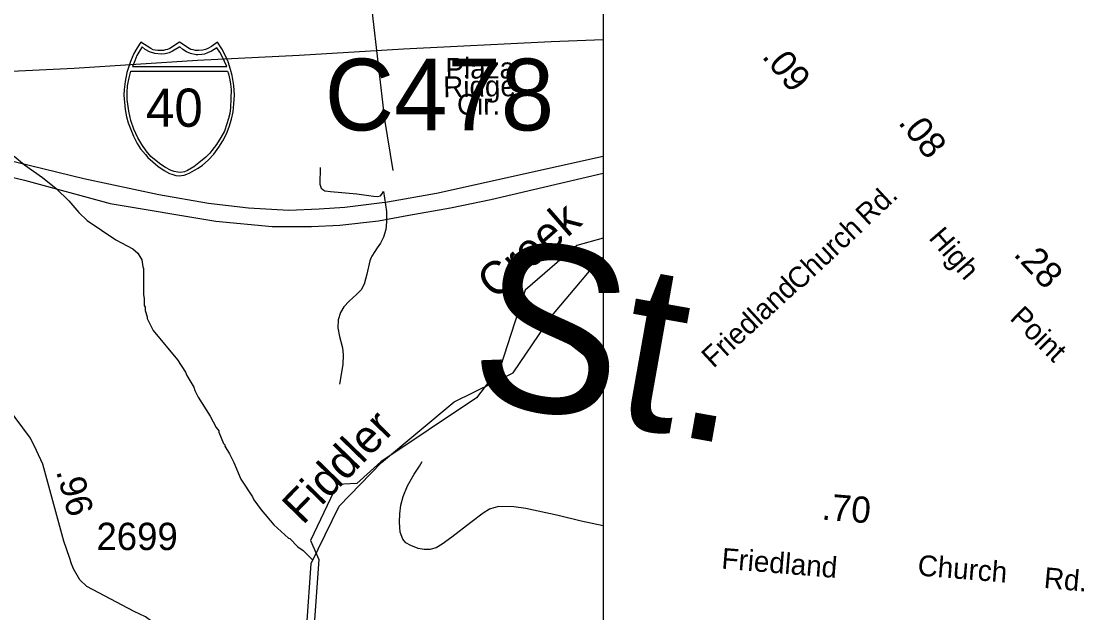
# Model space of a CAD drawing. Extents: x 1553981 to 1780076, y 812965 to 996873.
# Drawn here: x 1636043 to 1636650, y 846563 to 846901 of the extents above; entities that cross this region are included whole.
import ezdxf

# ---------------------------------------------------------------- set-up
doc = ezdxf.new("R2010")
doc.units = 0
for name, color, linetype in [('Default', 7, 'Continuous'), ('Exist Geographical Mountain Summit Label', 7, 'Continuous'), ('Exist Hydrographic Creek Single Shore', 7, 'Continuous'), ('Exist Hydrographic Creek Single Shore Label', 7, 'Continuous'), ('Exist Hydrographic Misc Water Feature', 7, 'Continuous'), ('Exist Road Non-System Type 51 Label', 7, 'Continuous'), ('Exist Road Primary Interstate Divided Center Attributed', 7, 'Continuous'), ('Exist Road Primary Interstate Shield CELL', 7, 'Continuous'), ('Exist Road Secondary Mileage Hundredths English Label', 7, 'Continuous'), ('Exist Road Secondary Structure Culvert Number Label', 7, 'Continuous'), ('Exist Road Secondary Type 51 Attributed', 7, 'Continuous'), ('Exist Road Secondary Type 51 Number Label', 7, 'Continuous'), ('Exist Utilities Electrical Transmission Line', 7, 'Continuous'), ('Map Preparation Border Antique Large Shape', 7, 'Continuous'), ('Map Preparation Border County Name Lower Right Label', 7, 'Continuous'), ('Map Preparation Border FIPS Code Label', 7, 'Continuous'), ('Map Preparation Border Revised Sign Off', 7, 'Continuous')]:
    doc.layers.add(name, color=color, linetype=linetype)

msp = doc.modelspace()

# ---------------------------------------------------------------- linework, layer by layer
at = {"layer": 'Default'}
msp.add_lwpolyline([(1632323.05, 848155.4), (1636375.85, 848155.4), (1636375.85, 845052.3), (1632323.05, 845052.3)], close=True, dxfattribs=at)
at = {"layer": 'Exist Hydrographic Creek Single Shore'}
msp.add_lwpolyline([(1636029.59, 846201.56), (1636078.51, 846261.77), (1636143.03, 846320.63), (1636154.6, 846354.87), (1636172.74, 846405.26), (1636203.88, 846520.44), (1636208.88, 846591.32), (1636224.87, 846624.22), (1636249.13, 846649.17), (1636290.69, 846683.7), (1636324.36, 846700.36), (1636346.42, 846732.9), (1636373.1, 846764.51), (1636375.85, 846766.54)], dxfattribs=at)
at = {"layer": 'Exist Hydrographic Misc Water Feature'}
msp.add_lwpolyline([(1636039.06, 846824.23), (1636045.02, 846819.18), (1636055.21, 846812.11), (1636063.15, 846805.8), (1636070.34, 846798.74), (1636076.04, 846791.95), (1636080.76, 846787.42), (1636097.16, 846776.3), (1636106.87, 846771.22), (1636109.84, 846768.7), (1636112.07, 846764.93), (1636112.54, 846760.93), (1636113.03, 846759.93), (1636112.93, 846744.94), (1636113.41, 846742.94), (1636113.38, 846738.94), (1636113.88, 846737.94), (1636113.86, 846735.94), (1636115.08, 846732.43), (1636115.08, 846731.43), (1636118.53, 846724.66), (1636132.39, 846707.81), (1636137.09, 846700.78), (1636137.83, 846698.77), (1636141.78, 846692.25), (1636142.26, 846690.24), (1636144.24, 846686.48), (1636151.14, 846675.69), (1636154.6, 846669.16), (1636156.08, 846667.15), (1636156.08, 846666.4), (1636158.78, 846659.88), (1636159.53, 846659.13), (1636159.51, 846658.38), (1636162.23, 846654.11), (1636164.7, 846649.09), (1636168.62, 846639.57), (1636175.3, 846629.52), (1636176.03, 846627.77), (1636180.24, 846621.99), (1636187.43, 846613.44), (1636195.86, 846605.87), (1636196.61, 846605.62), (1636201.32, 846600.83), (1636204.3, 846598.81), (1636209.35, 846593.69)], dxfattribs=at)
at = {"layer": 'Exist Road Primary Interstate Divided Center Attributed'}
for points in [[(1636375.85, 846824.07), (1636280.45, 846802.79), (1636252.47, 846798), (1636228.16, 846794.86), (1636213.35, 846793.96), (1636196, 846793.21), (1636173.1, 846794.41), (1636150.19, 846797.22), (1636121.8, 846802.2), (1636078.89, 846811.33), (1635970.16, 846837.8), (1635944.57, 846843.33), (1635918.77, 846847.37), (1635895.43, 846849.32), (1635871.9, 846850.24), (1635849.3, 846848.57), (1635828.29, 846845.97), (1635812.46, 846843.48)], [(1635819.59, 846832.32), (1635829.38, 846834.1), (1635855.63, 846836.6), (1635877.77, 846837.95), (1635891.84, 846838.7), (1635911.14, 846837.05), (1635923.18, 846835.85), (1635945.92, 846832.86), (1635968.81, 846828.52), (1636045.04, 846810.42), (1636093.96, 846797.08), (1636154.34, 846787.05), (1636186.57, 846784.09), (1636209.09, 846783.94), (1636225.24, 846784.84), (1636247.39, 846787.23), (1636264.74, 846790.52), (1636288.53, 846794.71), (1636311.57, 846799.5), (1636375.85, 846814.44)]]:
    msp.add_lwpolyline(points, dxfattribs=at)
at = {"layer": 'Exist Road Primary Interstate Shield CELL'}
for points in [[(1636133.49, 846813.02), (1636134.67, 846813.14), (1636136.27, 846813.45), (1636137.82, 846813.96), (1636139.58, 846814.74), (1636142.18, 846816.18), (1636144.28, 846817.41), (1636146.7, 846819.03), (1636149.96, 846821.99), (1636153.22, 846825.42), (1636156.09, 846829.3), (1636158.37, 846832.93), (1636160.38, 846837.07), (1636162.06, 846840.94), (1636163.39, 846845.35), (1636164.28, 846849.63), (1636164.72, 846854.09), (1636165.02, 846859.04), (1636164.68, 846864.61), (1636163.72, 846870.3), (1636162.81, 846873.85), (1636161.43, 846878.09), (1636160.3, 846880.8), (1636157.7, 846885.6), (1636155.36, 846889.3), (1636151.95, 846886.91), (1636149.73, 846885.73), (1636148.38, 846885.12), (1636146.98, 846884.85), (1636144.42, 846884.54), (1636142.81, 846884.61), (1636141.32, 846884.95), (1636140.05, 846885.22), (1636139.02, 846885.73), (1636133.49, 846889.3), (1636127.96, 846885.73), (1636126.8, 846885.19), (1636125.61, 846884.95), (1636124.46, 846884.63), (1636122.57, 846884.54), (1636121.13, 846884.58), (1636119.64, 846884.85), (1636118.47, 846885.09), (1636117.16, 846885.73), (1636111.52, 846889.3), (1636109.3, 846886.09), (1636107.49, 846882.91), (1636105.57, 846878.42), (1636104.38, 846874.94), (1636103.53, 846872.08), (1636102.48, 846866.84), (1636101.95, 846862.27), (1636101.85, 846859.04), (1636102.44, 846850.98), (1636103.32, 846846.68), (1636104.23, 846843.21), (1636107.21, 846835.7), (1636109.45, 846831.5), (1636111.38, 846828.48), (1636114.08, 846825.09), (1636115.54, 846823.46), (1636121.14, 846818.57), (1636124.88, 846816.01), (1636127.87, 846814.4), (1636129.27, 846813.87), (1636131.47, 846813.25)], [(1636112.19, 846886.71), (1636110.81, 846884.6), (1636109.23, 846881.74), (1636107.96, 846878.78), (1636106.67, 846875.51), (1636160.61, 846875.49), (1636159.36, 846878.29), (1636158.01, 846881.11), (1636156.6, 846883.68), (1636154.89, 846886.17), (1636151.86, 846884.26), (1636149.66, 846883.22), (1636147.89, 846882.61), (1636146.39, 846882.27), (1636144.07, 846882.09), (1636143.03, 846882.15), (1636139.78, 846882.88), (1636137.59, 846883.78), (1636135.5, 846885.17), (1636133.81, 846886.77), (1636129.54, 846884.18), (1636127.64, 846883.34), (1636125.46, 846882.79), (1636123.08, 846882.49), (1636119.4, 846882.89), (1636116.51, 846883.88), (1636114.03, 846885.17)], [(1636160.93, 846872.83), (1636161.51, 846871.31), (1636162.3, 846867.92), (1636162.72, 846865.32), (1636163.15, 846862.32), (1636163, 846857.18), (1636162.75, 846851.86), (1636162.26, 846848.7), (1636161.61, 846845.84), (1636160.71, 846842.66), (1636159.27, 846838.43), (1636157.28, 846834.85), (1636154.8, 846830.87), (1636152.11, 846827.39), (1636150.95, 846825.94), (1636148.73, 846823.6), (1636144.71, 846820.37), (1636141.77, 846818.17), (1636138.24, 846816.09), (1636136.45, 846815.3), (1636134.37, 846814.86), (1636132.66, 846814.98), (1636130.58, 846815.53), (1636128.9, 846815.99), (1636125.22, 846817.98), (1636122.24, 846819.97), (1636117.27, 846824.05), (1636114.59, 846827.19), (1636112.08, 846830.86), (1636109.85, 846834.63), (1636107.46, 846839.59), (1636105.78, 846844.57), (1636104.56, 846849.96), (1636103.73, 846856.54), (1636103.64, 846860.55), (1636103.88, 846864.4), (1636104.25, 846866.42), (1636104.74, 846868.93), (1636105.72, 846872.8)]]:
    msp.add_lwpolyline(points, close=True, dxfattribs=at)
at = {"layer": 'Exist Road Secondary Type 51 Attributed'}
msp.add_lwpolyline([(1636189.85, 846353.59), (1636177.07, 846391.96), (1636172.68, 846404.92), (1636168.55, 846419.71), (1636158.56, 846448.82), (1636144.46, 846492.68), (1636127.42, 846543.3), (1636122.71, 846551.83), (1636118.36, 846557.06), (1636117.72, 846558.29), (1636114.19, 846560.94), (1636107.73, 846563.88), (1636080.7, 846578.28), (1636076.59, 846582.1), (1636073.06, 846588.28), (1636071.89, 846591.22), (1636070.71, 846594.75), (1636067.48, 846604.15), (1636055.44, 846648.25), (1636051.91, 846655.89), (1636048.38, 846662.95), (1636025.72, 846693.31)], dxfattribs=at)
at = {"layer": 'Exist Utilities Electrical Transmission Line'}
msp.add_lwpolyline([(1636375.85, 846890.8), (1636346.1, 846889.49), (1636261.6, 846885.32), (1636202.07, 846881.86), (1636143.83, 846878.86), (1636073.32, 846874.27), (1635989.55, 846870.34), (1635919.82, 846867.25), (1635837.31, 846863.83), (1635766.81, 846860.73), (1635738.73, 846851.35), (1635627.77, 846812.03), (1635508.32, 846769.31), (1635424.73, 846738.89), (1635323.32, 846702.95), (1635267.09, 846683.16), (1635250.28, 846696.63), (1635201.6, 846738.27), (1635122.5, 846804.31), (1635050.76, 846862.25), (1635014.93, 846892.22), (1635012.58, 846924.48)], dxfattribs=at)
at = {"layer": 'Map Preparation Border County Name Lower Right Label'}
for points in [[(1636255.73, 846816.12), (1636251, 846845.23), (1636243.79, 846907.75)], [(1636214.05, 846817.7), (1636213.76, 846808.2), (1636214.49, 846805.96), (1636215.47, 846805.19), (1636216.73, 846804.44), (1636219.97, 846803.93), (1636234.95, 846802.6), (1636244.43, 846801.28), (1636246.68, 846801.26), (1636248.44, 846801.5), (1636249.18, 846802.51), (1636250.19, 846803.99), (1636251.88, 846792.5), (1636251.99, 846786.74), (1636251.57, 846782.25), (1636250.29, 846778), (1636248.51, 846774.51), (1636246.62, 846771.78), (1636245.24, 846769.79), (1636243.49, 846767.05), (1636243.22, 846766.31), (1636242.48, 846764.3), (1636240.68, 846756.8), (1636239.13, 846751.08), (1636237.37, 846747.84), (1636234.86, 846745.09), (1636230.58, 846741.38), (1636227.59, 846738.14), (1636225.55, 846734.9), (1636224.29, 846730.67), (1636224.02, 846726.18), (1636224.97, 846721.15), (1636226.69, 846714.67), (1636227.16, 846710.65), (1636226.9, 846705.16), (1636225.07, 846693.91)], [(1636339.08, 846730.94), (1636367, 846708.85), (1636375.85, 846707.89)], [(1636375.85, 846612.91), (1636363.28, 846615.66), (1636350.06, 846618.74), (1636331.58, 846622.84), (1636324.74, 846623.75), (1636316.09, 846623.93), (1636313.35, 846623.18), (1636310.73, 846622.36), (1636307.09, 846620.23), (1636300.05, 846614.77), (1636289.27, 846606.34), (1636283.74, 846602.37), (1636280.25, 846600.39), (1636276.72, 846599.41), (1636273.5, 846599.43), (1636269.98, 846599.95), (1636265.77, 846601.71), (1636263.02, 846603.22), (1636261.28, 846605.23), (1636259.82, 846609.24), (1636259.33, 846615), (1636259.63, 846619.75), (1636260.16, 846624.74), (1636261.43, 846629.74), (1636263.96, 846635.72), (1636267.74, 846642.44), (1636270.76, 846646.94), (1636272.29, 846649.66)]]:
    msp.add_lwpolyline(points, dxfattribs=at)
at = {"layer": 'Map Preparation Border FIPS Code Label'}
msp.add_lwpolyline([(1636375.85, 846777.29), (1636360.73, 846773.2), (1636331.22, 846747.53), (1636317.1, 846703.91), (1636303.35, 846686.14), (1636248.73, 846649.5), (1636235.01, 846637.19), (1636223.69, 846636.51), (1636208.53, 846604.58), (1636213.28, 846593.71), (1636210.81, 846559.25)], dxfattribs=at)
at = {"layer": 'Map Preparation Border Revised Sign Off'}
msp.add_lwpolyline([(1636375.85, 846777.29), (1636360.73, 846773.2), (1636331.22, 846747.53), (1636317.1, 846703.91), (1636303.35, 846686.14), (1636248.73, 846649.5), (1636235.01, 846637.19), (1636223.69, 846636.51), (1636208.53, 846604.58), (1636213.28, 846593.71), (1636210.81, 846559.25)], dxfattribs=at)

# ---------------------------------------------------------------- texts
at = {"layer": 'Exist Geographical Mountain Summit Label'}
msp.add_text('40', height=21.875, dxfattribs=at).set_placement((1636114.38, 846841))
at = {"layer": 'Exist Hydrographic Creek Single Shore Label'}
for s, rotation, p in [('Creek', 41.01981, (1636314.11, 846741.66)), ('Fiddler', 45.79826, (1636204.05, 846612.93))]:
    msp.add_text(s, height=18.75, rotation=rotation, dxfattribs=at).set_placement(p)
at = {"layer": 'Exist Road Non-System Type 51 Label'}
for s, height, rotation, p in [('Plaza', 11.875, 0.35332, (1636285.7, 846868.47)), ('Ridge', 11.875, 0.84669, (1636284.43, 846857.91)), ('Cir.', 11.875, 0.17101, (1636292.23, 846847.87)), ('St.', 95, 349.92734, (1636296.41, 846686.14))]:
    msp.add_text(s, height=height, rotation=rotation, dxfattribs=at).set_placement(p)
at = {"layer": 'Exist Road Secondary Mileage Hundredths English Label'}
for s, rotation, p in [('.09', 309.92028, (1636466.09, 846881.01)), ('.08', 308.99192, (1636544, 846843.27)), ('.28', 312.85191, (1636609.89, 846767.78)), ('.96', 285.27854, (1636062.95, 846644.09)), ('.70', 355.30187, (1636500.38, 846616.53))]:
    msp.add_text(s, height=15, rotation=rotation, dxfattribs=at).set_placement(p)
at = {"layer": 'Exist Road Secondary Structure Culvert Number Label'}
msp.add_text('C478', height=41.01, dxfattribs=at).set_placement((1636216.62, 846838.93))
at = {"layer": 'Exist Road Secondary Type 51 Number Label'}
msp.add_text('2699', height=15.625, dxfattribs=at).set_placement((1636086.11, 846599.05))
at = {"layer": 'Map Preparation Border Antique Large Shape'}
for s, rotation, p in [('Rd.', 42.99858, (1636526.94, 846784.06)), ('Church', 43.04917, (1636487.43, 846746.76)), ('High', 310.89577, (1636561.42, 846777.24)), ('Friedland', 42.78586, (1636438.83, 846702.6)), ('Point', 315.41441, (1636607.71, 846731.17)), ('Friedland', 355.30187, (1636443.11, 846588.49)), ('Church', 355.34616, (1636555.24, 846584.55)), ('Rd.', 354.8462, (1636627.39, 846577.46))]:
    msp.add_text(s, height=11.875, rotation=rotation, dxfattribs=at).set_placement(p)

doc.saveas('drawing.dxf')
